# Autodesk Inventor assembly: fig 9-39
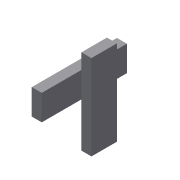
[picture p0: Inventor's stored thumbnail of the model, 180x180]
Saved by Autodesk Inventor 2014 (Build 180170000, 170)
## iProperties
Created: 2013-07
Part Number: fig 9-39
Document SubType Name: Assembly
Designer: CADCIM
Author: CADCIM
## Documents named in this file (2)
- E:\APS\Autodesk Inventor 2014-Project\inventor_2014_partfiles\Inventor_2014_prt\c09_Inv_2014_prt\c09_inv_2014_prt\fig 9-39.iam
- E:\APS\Autodesk Inventor 2014-Project\inventor_2014_partfiles\Inventor_2014_prt\c09_Inv_2014_prt\c09_inv_2014_prt\12.ipt
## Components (2 placed, 1 different names)
1. 12:1
2. 12:2
